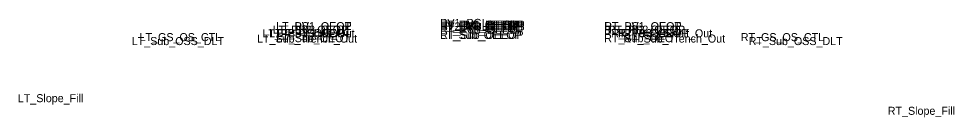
# Model space of a CAD drawing. Extents: x -26 to 1618, y 0 to 9529.
# Drawn here: x 1169.2 to 1237.6, y 3004.7 to 3011.9 of the extents above; entities that cross this region are included whole.
import ezdxf

# ---------------------------------------------------------------- set-up
doc = ezdxf.new("R2010")
doc.units = 0
doc.layers.add('Default', color=7, linetype='Continuous')

msp = doc.modelspace()

# ---------------------------------------------------------------- texts
at = {"layer": 'Default'}
for s, height, p in [('LT_PS2_OEOP', 0.58594, (1187.735, 3010.815)), ('LT_PS1_OEOP', 0.58594, (1187.99, 3011.07)), ('LT_PV1_OEOT', 0.58594, (1188, 3011.071)), ('LT_PV2_OEOT', 0.58594, (1188, 3010.821)), ('PV1_PGL', 0.5859, (1200, 3011.311)), ('RT_PV1_IEEOP', 0.58594, (1200, 3011.186)), ('LT_PV1_IEEOP', 0.58594, (1200, 3011.186)), ('RT_PV1_OEEOP', 0.58594, (1200, 3011.186)), ('LT_PV1_OEEOP', 0.58594, (1200, 3011.186)), ('RT_PV2_IEEOP', 0.58594, (1200, 3011.061)), ('LT_PV2_IEEOP', 0.58594, (1200, 3011.061)), ('RT_PV2_OEEOP', 0.58594, (1200, 3011.061)), ('PV2_PGL', 0.5859, (1200, 3011.061)), ('LT_PV2_OEEOP', 0.58594, (1200, 3011.061)), ('RT_PV3_OEEOP', 0.58594, (1200, 3010.811)), ('LT_PV3_OEEOP', 0.58594, (1200, 3010.811)), ('RT_PV1_OEOT', 0.58594, (1212, 3011.071)), ('RT_PV2_OEOT', 0.58594, (1212, 3010.821)), ('RT_PS1_OEOP', 0.58594, (1212.01, 3011.07)), ('RT_PS2_OEOP', 0.58594, (1212.265, 3010.815)), ('LT_GS_OS_CTL', 0.58594, (1178, 3010.271)), ('LT_Sub_Trench_Out', 0.58594, (1186.597, 3010.168)), ('LT_PS3_Shelf_Out', 0.58594, (1186.98, 3010.55)), ('LT_PS3_OEOP', 0.58594, (1187.48, 3010.56)), ('LT_PV3_OEOT', 0.58594, (1188, 3010.571)), ('LT_Sub_OEOT', 0.58594, (1188, 3010.196)), ('LT_Sub_OEEOP', 0.58594, (1200, 3010.436)), ('RT_Sub_OEEOP', 0.58594, (1200, 3010.436)), ('RT_PV3_OEOT', 0.58594, (1212, 3010.571)), ('RT_Sub_OEOT', 0.58594, (1212, 3010.196)), ('RT_PS3_OEOP', 0.58594, (1212.52, 3010.56)), ('RT_PS3_Shelf_Out', 0.58594, (1213.02, 3010.55)), ('RT_Sub_Trench_Out', 0.58594, (1213.403, 3010.168)), ('RT_GS_OS_CTL', 0.58594, (1222, 3010.271)), ('LT_Sub_OSS_DLT', 0.58594, (1177.426, 3009.984)), ('RT_Sub_OSS_DLT', 0.58594, (1222.574, 3009.984)), ('LT_Slope_Fill', 0.58594, (1169.088, 3005.815)), ('RT_Slope_Fill', 0.58594, (1232.754, 3004.894))]:
    msp.add_text(s, height=height, dxfattribs=at).set_placement(p)

doc.saveas('drawing.dxf')
